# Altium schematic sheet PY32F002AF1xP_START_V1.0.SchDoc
size A4
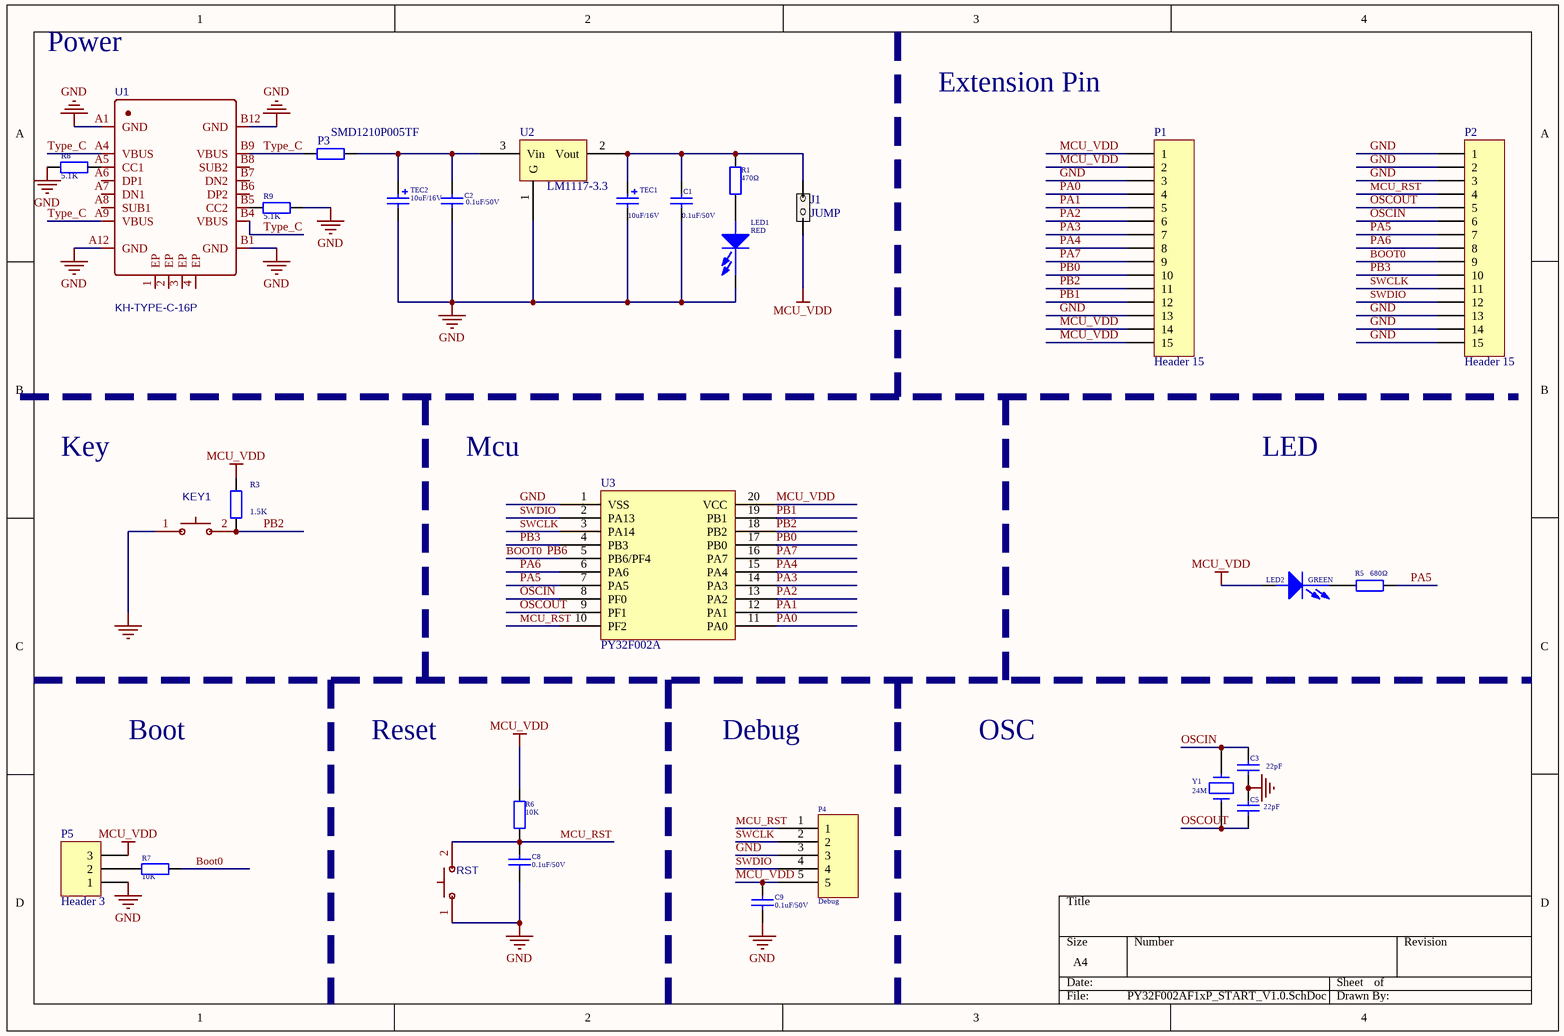
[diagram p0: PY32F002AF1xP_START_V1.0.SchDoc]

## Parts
C1  0.1uF/50V  [0603C]
C2  0.1uF/50V  [0603C]
C3  22pF  [0603C]
C5  22pF  [0603C]
C8  0.1uF/50V  [0603C]
C9  0.1uF/50V  [0603C]
J1  JUMP  [HDR1X2]
KEY1  1TS002B-2600-5001  [SW]  (value not drawn)
LED1  RED  [0603_LED]
LED2  GREEN  [0603_LED]
P1  Header 15  [HDR1X15]
P2  Header 15  [HDR1X15]
P3  SMD1210P005TF  [SDM1210P005TF]
P4  Debug  [HDR1X5]
P5  Header 3  [HDR1X3]
R1  470Ω  [0603R]
R3  1.5K  [0603R]
R5  680Ω  [0603R]
R6  10K  [0603R]
R7  10K  [0603R]
R8  5.1K  [0603R]
R9  5.1K  [0603R]
RST  1TS002B-2600-5001  [SW]  (value not drawn)
TEC1  value 10uF/16V  [0603]  (hidden comment: 10uF)
TEC2  value 10uF/16V  [0603]  (hidden comment: 10uF)
U1  KH-TYPE-C-16P  [USB-C-SMD_KH-TYPE-C-16P]
U2  LM1117-3.3  [LM1117-3.3]
U3  PY32F002A  [TSSOP20]
Y1  24M  [25MHZ_2]

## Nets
GND: C1.1 C2.1 C3.1 C5.2 C8.1 C9.1 KEY1.1(A) LED1.2(CATHODE) P1.3 P1.13 P2.1 P2.2 P2.3 P2.13 P2.14 P2.15 P4.3 P5.1 R8.1 R9.2 RST.1(A) TEC1.2 TEC2.2 U1.A1(GND) U1.A12(GND) U1.B1(GND) U1.B12(GND) U2.1(G) U3.1(VSS)
MCU_VDD: C9.2 J1.1 LED2.1(ANODE) P1.1 P1.2 P1.14 P1.15 P4.5 P5.3 R3.1 R6.2 U3.20(VCC)
BOOT0: P2.9 R7.2 U3.5(PB6/PF4)  [also labelled PB6]
MCU_RST: C8.2 P2.4 P4.1 R6.1 RST.2(B) U3.10(PF2)
OSCIN: C3.2 P2.6 U3.8(PF0) Y1.1
OSCOUT: C5.1 P2.5 U3.9(PF1) Y1.2
PA0: P1.4 U3.11(PA0)
PA1: P1.5 U3.12(PA1)
PA2: P1.6 U3.13(PA2)
PA3: P1.7 U3.14(PA3)
PA4: P1.8 U3.15(PA4)
PA5: P2.7 R5.2 U3.7(PA5)
PA6: P2.8 U3.6(PA6)
PA7: P1.9 U3.16(PA7)
PB0: P1.10 U3.17(PB0)
PB1: P1.12 U3.19(PB1)
PB2: KEY1.2(B) P1.11 R3.2 U3.18(PB2)
PB3: P2.10 U3.4(PB3)
SWCLK: P2.11 P4.2 U3.3(PA14)
SWDIO: P2.12 P4.4 U3.2(PA13)
Type_C: P3.1 U1.A4(VBUS) U1.A9(VBUS) U1.B4(VBUS) U1.B9(VBUS)
NetC1_2: C1.2 J1.2 R1.1 TEC1.1 U2.2(Vout)
NetC2_2: C2.2 P3.2 TEC2.1 U2.3(Vin)
NetLED1_1: LED1.1(ANODE) R1.2
NetLED2_2: LED2.2(CATHODE) R5.1
NetP5_2: P5.2 R7.1
NetR8_2: R8.2 U1.A5(CC1)
NetR9_1: R9.1 U1.B5(CC2)

Not connected (* = marked no-connect by the designer): U1 1(EP) 2(EP) 3(EP) 4(EP) A6(DP1) A7(DN1) A8(SUB1) B6(DP2) B7(DN2) B8(SUB2)

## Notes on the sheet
- Power
- Extension Pin
- Key
- Mcu
- LED
- Boot
- Reset
- Debug
- OSC

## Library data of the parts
C1 C3 C5 = Cap: Capacitor
C2 C8 C9 = CAP: Capacitor; Value: 2.2uF
KEY1 RST = 1TS002B-2600-5001: BOM_Manufacturer: HYP; Contributor: LCSC
LED1 LED2 = PDI-E803_Dup1
P1 P2 = Header 15: Header, 15-Pin
P4 = CON5
P5 = Header 3: Header, 3-Pin
R1 R3 R5 = Res: Resistor; 器件封装(外观): 0603; Value: 10K
R6 R7 = Res: Resistor; 器件封装(外观): 0603
R8 R9 = Res_1: Resistor; 器件封装(外观): 0603; Value: 10K
TEC1 TEC2 = 贴片钽电容: 器件封装(外观): 3528
U1 = KH-TYPE-C-16P: BOM_Manufacturer: Shenzhen Kinghelm Elec; Contributor: LCSC
Y1 = CRYSTAL: Value: X503225MSB2GI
